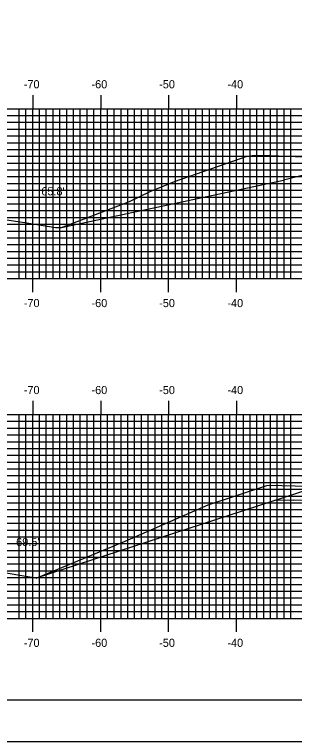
# Model space of a CAD drawing. Extents: x 852540 to 852884, y 364661 to 364881.
# Drawn here: x 852633.6 to 852674.8, y 364661.3 to 364768.2 of the extents above; entities that cross this region are included whole.
import ezdxf

# ---------------------------------------------------------------- set-up
doc = ezdxf.new("R2010")
doc.units = 0
for name, color, linetype in [('BORDER', 7, 'Continuous'), ('D_Roadway_SlopeLines', 7, 'Continuous'), ('D_Text_Standard', 7, 'Continuous'), ('H_V ANNOTATION', 7, 'Continuous'), ('MAJOR', 7, 'Continuous'), ('MINOR', 7, 'Continuous'), ('PLOT BOUNDARY', 7, 'Continuous'), ('S_Roadway_Centerline', 7, 'Continuous')]:
    doc.layers.add(name, color=color, linetype=linetype)

msp = doc.modelspace()

# ---------------------------------------------------------------- linework, layer by layer
at = {"layer": 'BORDER'}
msp.add_lwpolyline([(852556.67, 364667.37), (852876.67, 364667.37), (852876.67, 364877.37), (852556.67, 364877.37)], close=True, dxfattribs=at)
at = {"layer": 'D_Roadway_SlopeLines'}
for p, q in [((852640.49, 364736.91), (852673.2, 364743.83)), ((852679.59, 364699.22), (852636.79, 364685.3)), ((852674.67, 364696.76), (852671.86, 364696.71)), ((852674.67, 364696.76), (852690.59, 364697.09))]:
    msp.add_line(p, q, dxfattribs=at)
msp.add_lwpolyline([(852687.43, 364747.39), (852673.2, 364743.83)], dxfattribs=at)
at = {"layer": 'MAJOR'}
for p, q in [((852636.27, 364756.37), (852636.27, 364754.37)), ((852646.27, 364756.37), (852646.27, 364754.37)), ((852656.27, 364756.37), (852656.27, 364754.37)), ((852666.27, 364756.37), (852666.27, 364754.37)), ((852566.27, 364754.37), (852846.27, 364754.37)), ((852566.27, 364754.37), (852846.27, 364754.37)), ((852636.27, 364729.37), (852636.27, 364754.37)), ((852646.27, 364729.37), (852646.27, 364754.37)), ((852656.27, 364729.37), (852656.27, 364754.37)), ((852666.27, 364729.37), (852666.27, 364754.37)), ((852566.27, 364749.37), (852846.27, 364749.37)), ((852566.27, 364744.37), (852846.27, 364744.37)), ((852566.27, 364739.37), (852846.27, 364739.37)), ((852566.27, 364734.37), (852846.27, 364734.37)), ((852566.27, 364729.37), (852846.27, 364729.37)), ((852566.27, 364729.37), (852846.27, 364729.37)), ((852636.27, 364727.37), (852636.27, 364729.37)), ((852646.27, 364727.37), (852646.27, 364729.37)), ((852656.27, 364727.37), (852656.27, 364729.37)), ((852666.27, 364727.37), (852666.27, 364729.37)), ((852636.27, 364711.37), (852636.27, 364709.37)), ((852646.27, 364711.37), (852646.27, 364709.37)), ((852656.27, 364711.37), (852656.27, 364709.37)), ((852666.27, 364711.37), (852666.27, 364709.37)), ((852566.27, 364709.37), (852846.27, 364709.37)), ((852566.27, 364709.37), (852846.27, 364709.37)), ((852636.27, 364679.37), (852636.27, 364709.37)), ((852646.27, 364679.37), (852646.27, 364709.37)), ((852656.27, 364679.37), (852656.27, 364709.37)), ((852666.27, 364679.37), (852666.27, 364709.37)), ((852566.27, 364704.37), (852846.27, 364704.37)), ((852566.27, 364699.37), (852846.27, 364699.37)), ((852566.27, 364694.37), (852846.27, 364694.37)), ((852566.27, 364689.37), (852846.27, 364689.37)), ((852566.27, 364684.37), (852846.27, 364684.37)), ((852566.27, 364679.37), (852846.27, 364679.37)), ((852566.27, 364679.37), (852846.27, 364679.37)), ((852636.27, 364677.37), (852636.27, 364679.37)), ((852646.27, 364677.37), (852646.27, 364679.37)), ((852656.27, 364677.37), (852656.27, 364679.37)), ((852666.27, 364677.37), (852666.27, 364679.37))]:
    msp.add_line(p, q, dxfattribs=at)
at = {"layer": 'MINOR'}
for p, q in [((852634.27, 364729.37), (852634.27, 364754.37)), ((852635.27, 364729.37), (852635.27, 364754.37)), ((852637.27, 364729.37), (852637.27, 364754.37)), ((852638.27, 364729.37), (852638.27, 364754.37)), ((852639.27, 364729.37), (852639.27, 364754.37)), ((852640.27, 364729.37), (852640.27, 364754.37)), ((852641.27, 364729.37), (852641.27, 364754.37)), ((852642.27, 364729.37), (852642.27, 364754.37)), ((852643.27, 364729.37), (852643.27, 364754.37)), ((852644.27, 364729.37), (852644.27, 364754.37)), ((852645.27, 364729.37), (852645.27, 364754.37)), ((852647.27, 364729.37), (852647.27, 364754.37)), ((852648.27, 364729.37), (852648.27, 364754.37)), ((852649.27, 364729.37), (852649.27, 364754.37)), ((852650.27, 364729.37), (852650.27, 364754.37)), ((852651.27, 364729.37), (852651.27, 364754.37)), ((852652.27, 364729.37), (852652.27, 364754.37)), ((852653.27, 364729.37), (852653.27, 364754.37)), ((852654.27, 364729.37), (852654.27, 364754.37)), ((852655.27, 364729.37), (852655.27, 364754.37)), ((852657.27, 364729.37), (852657.27, 364754.37)), ((852658.27, 364729.37), (852658.27, 364754.37)), ((852659.27, 364729.37), (852659.27, 364754.37)), ((852660.27, 364729.37), (852660.27, 364754.37)), ((852661.27, 364729.37), (852661.27, 364754.37)), ((852662.27, 364729.37), (852662.27, 364754.37)), ((852663.27, 364729.37), (852663.27, 364754.37)), ((852664.27, 364729.37), (852664.27, 364754.37)), ((852665.27, 364729.37), (852665.27, 364754.37)), ((852667.27, 364729.37), (852667.27, 364754.37)), ((852668.27, 364729.37), (852668.27, 364754.37)), ((852669.27, 364729.37), (852669.27, 364754.37)), ((852670.27, 364729.37), (852670.27, 364754.37)), ((852671.27, 364729.37), (852671.27, 364754.37)), ((852672.27, 364729.37), (852672.27, 364754.37)), ((852673.27, 364729.37), (852673.27, 364754.37)), ((852674.27, 364729.37), (852674.27, 364754.37)), ((852566.27, 364753.37), (852846.27, 364753.37)), ((852566.27, 364752.37), (852846.27, 364752.37)), ((852566.27, 364751.37), (852846.27, 364751.37)), ((852566.27, 364750.37), (852846.27, 364750.37)), ((852566.27, 364748.37), (852846.27, 364748.37)), ((852566.27, 364747.37), (852846.27, 364747.37)), ((852566.27, 364746.37), (852846.27, 364746.37)), ((852566.27, 364745.37), (852846.27, 364745.37)), ((852566.27, 364743.37), (852846.27, 364743.37)), ((852566.27, 364742.37), (852846.27, 364742.37)), ((852566.27, 364741.37), (852846.27, 364741.37)), ((852566.27, 364740.37), (852846.27, 364740.37)), ((852566.27, 364738.37), (852846.27, 364738.37)), ((852566.27, 364737.37), (852846.27, 364737.37)), ((852566.27, 364736.37), (852846.27, 364736.37)), ((852566.27, 364735.37), (852846.27, 364735.37)), ((852566.27, 364733.37), (852846.27, 364733.37)), ((852566.27, 364732.37), (852846.27, 364732.37)), ((852566.27, 364731.37), (852846.27, 364731.37)), ((852566.27, 364730.37), (852846.27, 364730.37)), ((852566.27, 364708.37), (852846.27, 364708.37)), ((852634.27, 364679.37), (852634.27, 364709.37)), ((852635.27, 364679.37), (852635.27, 364709.37)), ((852637.27, 364679.37), (852637.27, 364709.37)), ((852638.27, 364679.37), (852638.27, 364709.37)), ((852639.27, 364679.37), (852639.27, 364709.37)), ((852640.27, 364679.37), (852640.27, 364709.37)), ((852641.27, 364679.37), (852641.27, 364709.37)), ((852642.27, 364679.37), (852642.27, 364709.37)), ((852643.27, 364679.37), (852643.27, 364709.37)), ((852644.27, 364679.37), (852644.27, 364709.37)), ((852645.27, 364679.37), (852645.27, 364709.37)), ((852647.27, 364679.37), (852647.27, 364709.37)), ((852648.27, 364679.37), (852648.27, 364709.37)), ((852649.27, 364679.37), (852649.27, 364709.37)), ((852650.27, 364679.37), (852650.27, 364709.37)), ((852651.27, 364679.37), (852651.27, 364709.37)), ((852652.27, 364679.37), (852652.27, 364709.37)), ((852653.27, 364679.37), (852653.27, 364709.37)), ((852654.27, 364679.37), (852654.27, 364709.37)), ((852655.27, 364679.37), (852655.27, 364709.37)), ((852657.27, 364679.37), (852657.27, 364709.37)), ((852658.27, 364679.37), (852658.27, 364709.37)), ((852659.27, 364679.37), (852659.27, 364709.37)), ((852660.27, 364679.37), (852660.27, 364709.37)), ((852661.27, 364679.37), (852661.27, 364709.37)), ((852662.27, 364679.37), (852662.27, 364709.37)), ((852663.27, 364679.37), (852663.27, 364709.37)), ((852664.27, 364679.37), (852664.27, 364709.37)), ((852665.27, 364679.37), (852665.27, 364709.37)), ((852667.27, 364679.37), (852667.27, 364709.37)), ((852668.27, 364679.37), (852668.27, 364709.37)), ((852669.27, 364679.37), (852669.27, 364709.37)), ((852670.27, 364679.37), (852670.27, 364709.37)), ((852671.27, 364679.37), (852671.27, 364709.37)), ((852672.27, 364679.37), (852672.27, 364709.37)), ((852673.27, 364679.37), (852673.27, 364709.37)), ((852674.27, 364679.37), (852674.27, 364709.37)), ((852566.27, 364707.37), (852846.27, 364707.37)), ((852566.27, 364706.37), (852846.27, 364706.37)), ((852566.27, 364705.37), (852846.27, 364705.37)), ((852566.27, 364703.37), (852846.27, 364703.37)), ((852566.27, 364702.37), (852846.27, 364702.37)), ((852566.27, 364701.37), (852846.27, 364701.37)), ((852566.27, 364700.37), (852846.27, 364700.37)), ((852566.27, 364698.37), (852846.27, 364698.37)), ((852566.27, 364697.37), (852846.27, 364697.37)), ((852566.27, 364696.37), (852846.27, 364696.37)), ((852566.27, 364695.37), (852846.27, 364695.37)), ((852566.27, 364693.37), (852846.27, 364693.37)), ((852566.27, 364692.37), (852846.27, 364692.37)), ((852566.27, 364691.37), (852846.27, 364691.37)), ((852566.27, 364690.37), (852846.27, 364690.37)), ((852566.27, 364688.37), (852846.27, 364688.37)), ((852566.27, 364687.37), (852846.27, 364687.37)), ((852566.27, 364686.37), (852846.27, 364686.37)), ((852566.27, 364685.37), (852846.27, 364685.37)), ((852566.27, 364683.37), (852846.27, 364683.37)), ((852566.27, 364682.37), (852846.27, 364682.37)), ((852566.27, 364681.37), (852846.27, 364681.37)), ((852566.27, 364680.37), (852846.27, 364680.37))]:
    msp.add_line(p, q, dxfattribs=at)
at = {"layer": 'PLOT BOUNDARY'}
msp.add_lwpolyline([(852540.48, 364661.25), (852880.48, 364661.25), (852880.48, 364881.25), (852540.48, 364881.25)], close=True, dxfattribs=at)
at = {"layer": 'S_Roadway_Centerline'}
for points in [[(852628.65, 364738.56), (852635.1, 364737.63), (852639.61, 364736.87), (852640.49, 364736.91), (852650.5, 364740.73), (852653.56, 364742.2), (852657.15, 364743.66), (852667.85, 364747.39), (852668.92, 364747.53), (852671.2, 364747.48), (852678.68, 364747.21)], [(852627.46, 364686.91), (852634.66, 364685.69), (852636.71, 364685.31), (852636.79, 364685.3), (852649.85, 364690.75), (852662.08, 364696.09), (852670.74, 364698.9), (852671.17, 364698.98), (852671.34, 364698.98), (852672.92, 364698.93), (852684.63, 364698.62)]]:
    msp.add_lwpolyline(points, dxfattribs=at)

# ---------------------------------------------------------------- texts
at = {"layer": 'D_Text_Standard'}
for s, p in [("65.8'", (852637.53, 364741.62)), ("69.5'", (852633.83, 364690.01))]:
    msp.add_text(s, height=1.2, dxfattribs=at).set_placement(p)
at = {"layer": 'H_V ANNOTATION'}
for s, p in [('-70', (852634.95, 364757.37)), ('-60', (852644.92, 364757.37)), ('-50', (852654.88, 364757.37)), ('-40', (852664.92, 364757.37)), ('-70', (852634.95, 364725.17)), ('-60', (852644.92, 364725.17)), ('-50', (852654.88, 364725.17)), ('-40', (852664.92, 364725.17)), ('-70', (852634.95, 364712.37)), ('-60', (852644.92, 364712.37)), ('-50', (852654.88, 364712.37)), ('-40', (852664.92, 364712.37)), ('-70', (852634.95, 364675.17)), ('-60', (852644.92, 364675.17)), ('-50', (852654.88, 364675.17)), ('-40', (852664.92, 364675.17))]:
    msp.add_text(s, height=1.2, dxfattribs=at).set_placement(p)

doc.saveas('drawing.dxf')
